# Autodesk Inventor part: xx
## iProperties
Shininess: 64.0
Length Units: 11272
Angle Units: 11279
Time Units: 11290
Mass Units: 11286
Length Display Precision: 3
Angle Display Precision: 2
Compacted: True
Part Number: xx
Document SubType Name: Modeling
Created: 2004-04
Designer: Sean Thompson
Manufacturer: Standard
Standards Organization: Custom
Material: Stainless Steel, Austenitic
Description: Wing Nut, 5/16-18 UNC, Light, Type A
Density: 0.0
Volumn: 0.0
Area: 0.0
PropertySet Name: Model Information
Control State: 0
Master: False
Checked Out: False
Author: Sean Thompson
Subject: Wing Nut
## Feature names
1. Extrusion1
2. Extrusion2
3. Extrusion3
4. Fillet1
5. Fillet2
6. Hole1
